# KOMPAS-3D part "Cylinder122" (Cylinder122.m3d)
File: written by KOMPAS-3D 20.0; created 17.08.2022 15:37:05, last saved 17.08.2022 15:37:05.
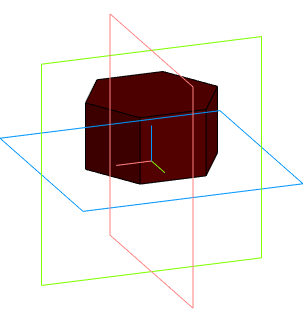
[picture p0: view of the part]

Document properties: Автор: artemsv220@gmail.com; Полное имя файла: \\192.168.2.25\новая общая папка\Медиа\Светильники\Кашпо\Кашпо и вазоны\DWG\Cylinder122.m3d

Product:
- Part/product: Cylinder122

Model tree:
1. Операция без истории:1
